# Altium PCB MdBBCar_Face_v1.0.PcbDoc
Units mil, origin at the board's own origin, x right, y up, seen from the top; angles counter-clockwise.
Board outline 2202.88 x 1898.45 mil, 4 copper layers (Top Layer, GND, SIG, Bottom Layer), stack 23.756 mil thick; 53 components, 60 nets, 263 pads, 211 vias.
Unrouted connection lines stored in the file: 2.
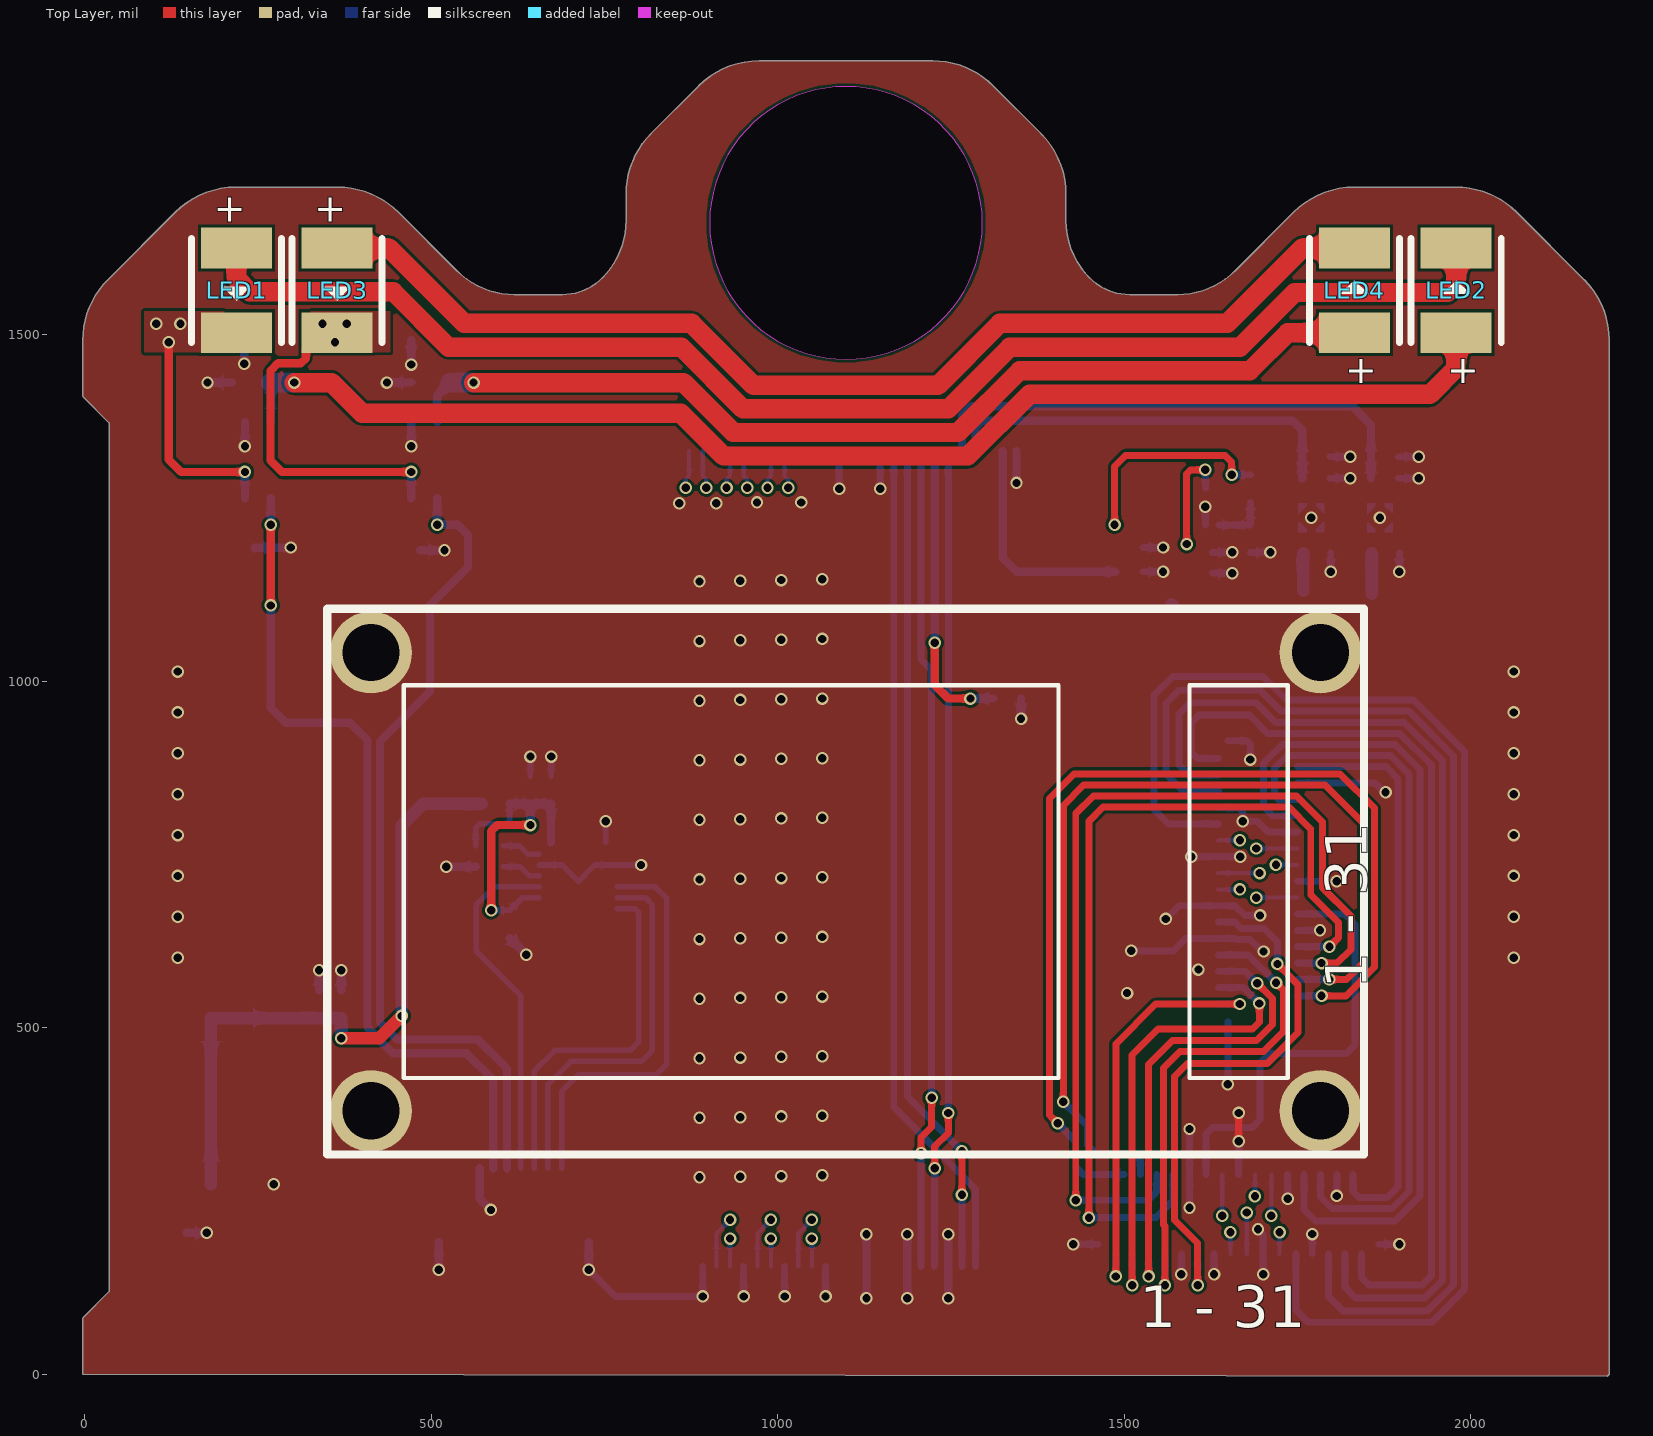
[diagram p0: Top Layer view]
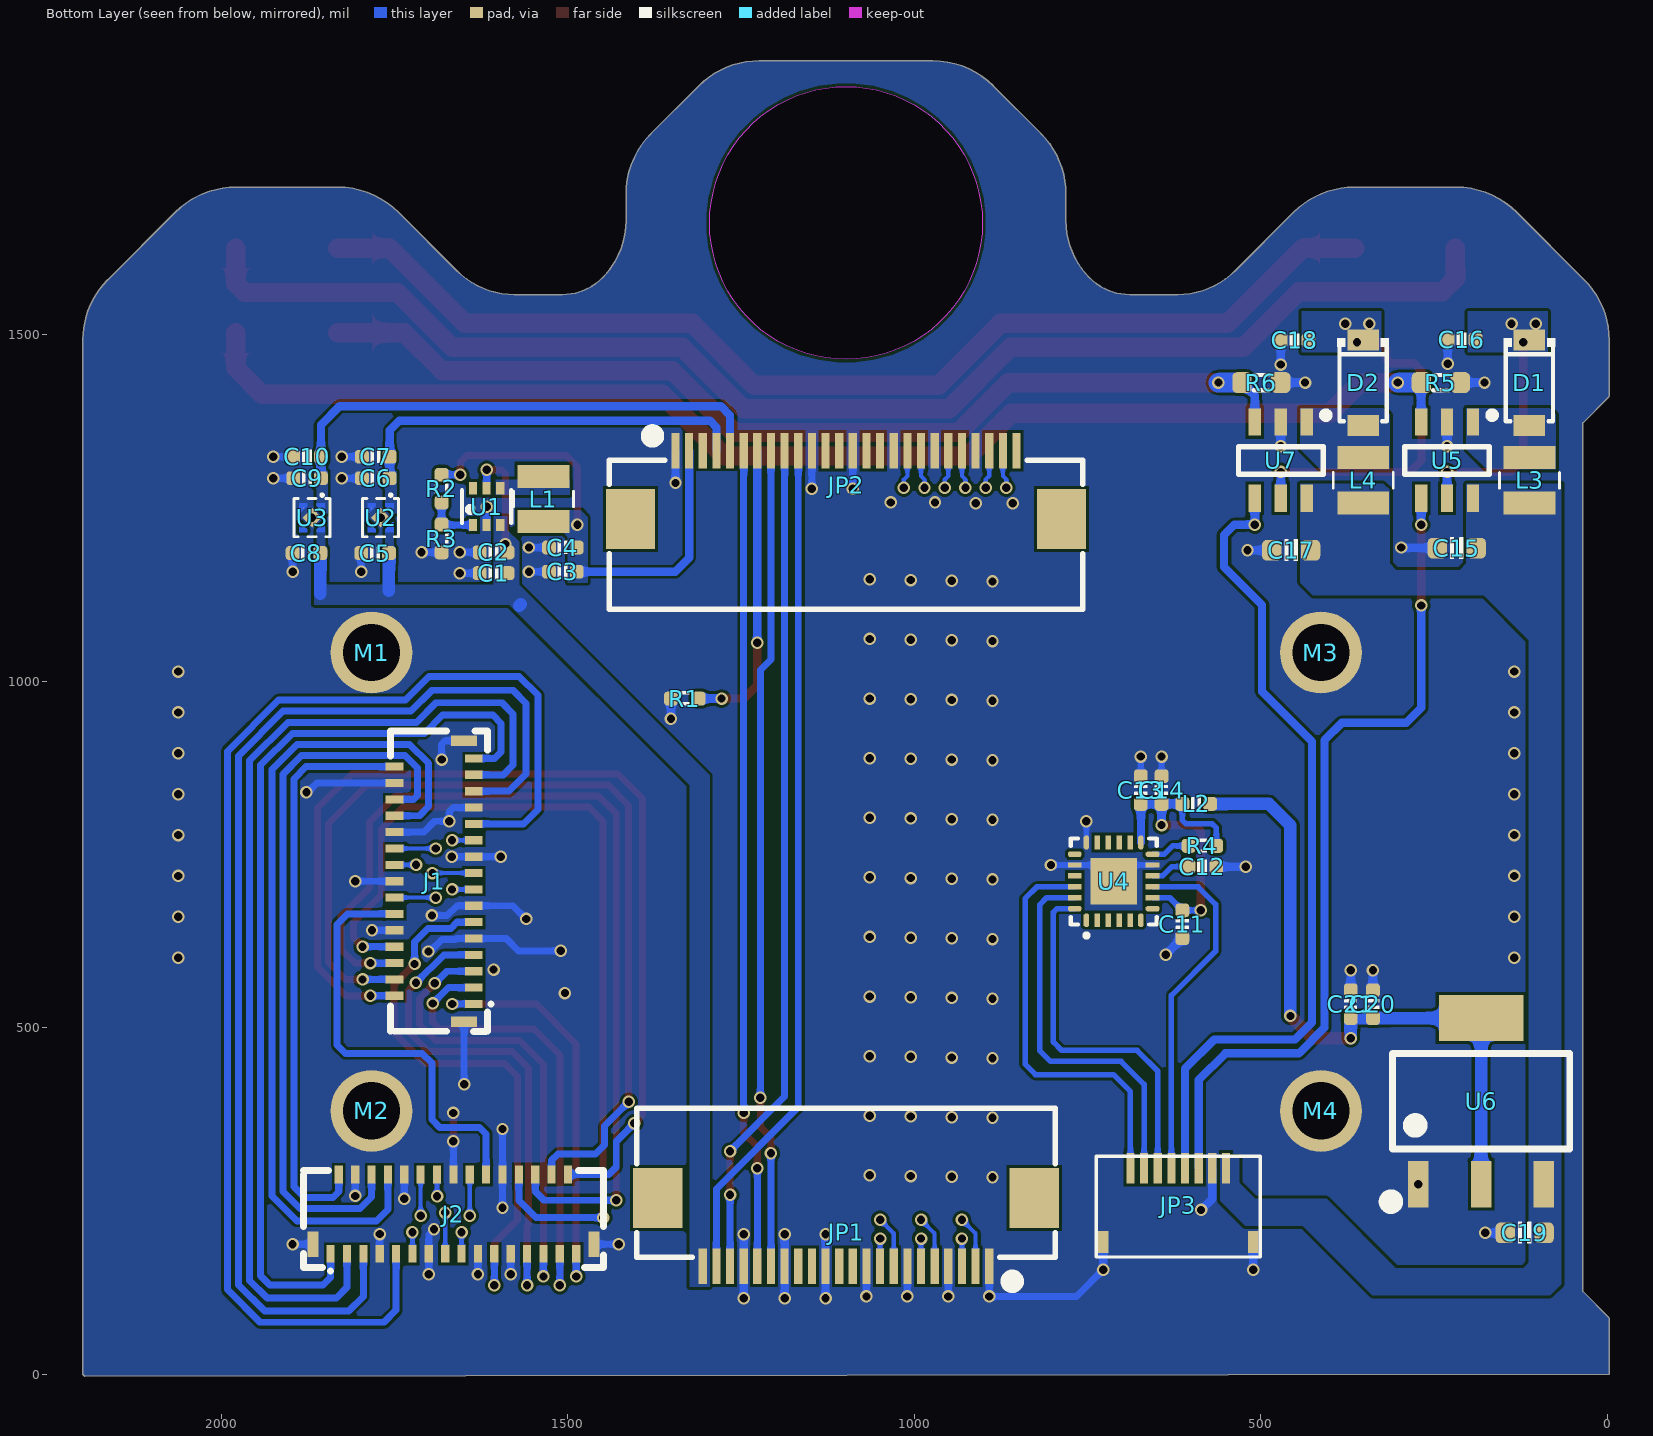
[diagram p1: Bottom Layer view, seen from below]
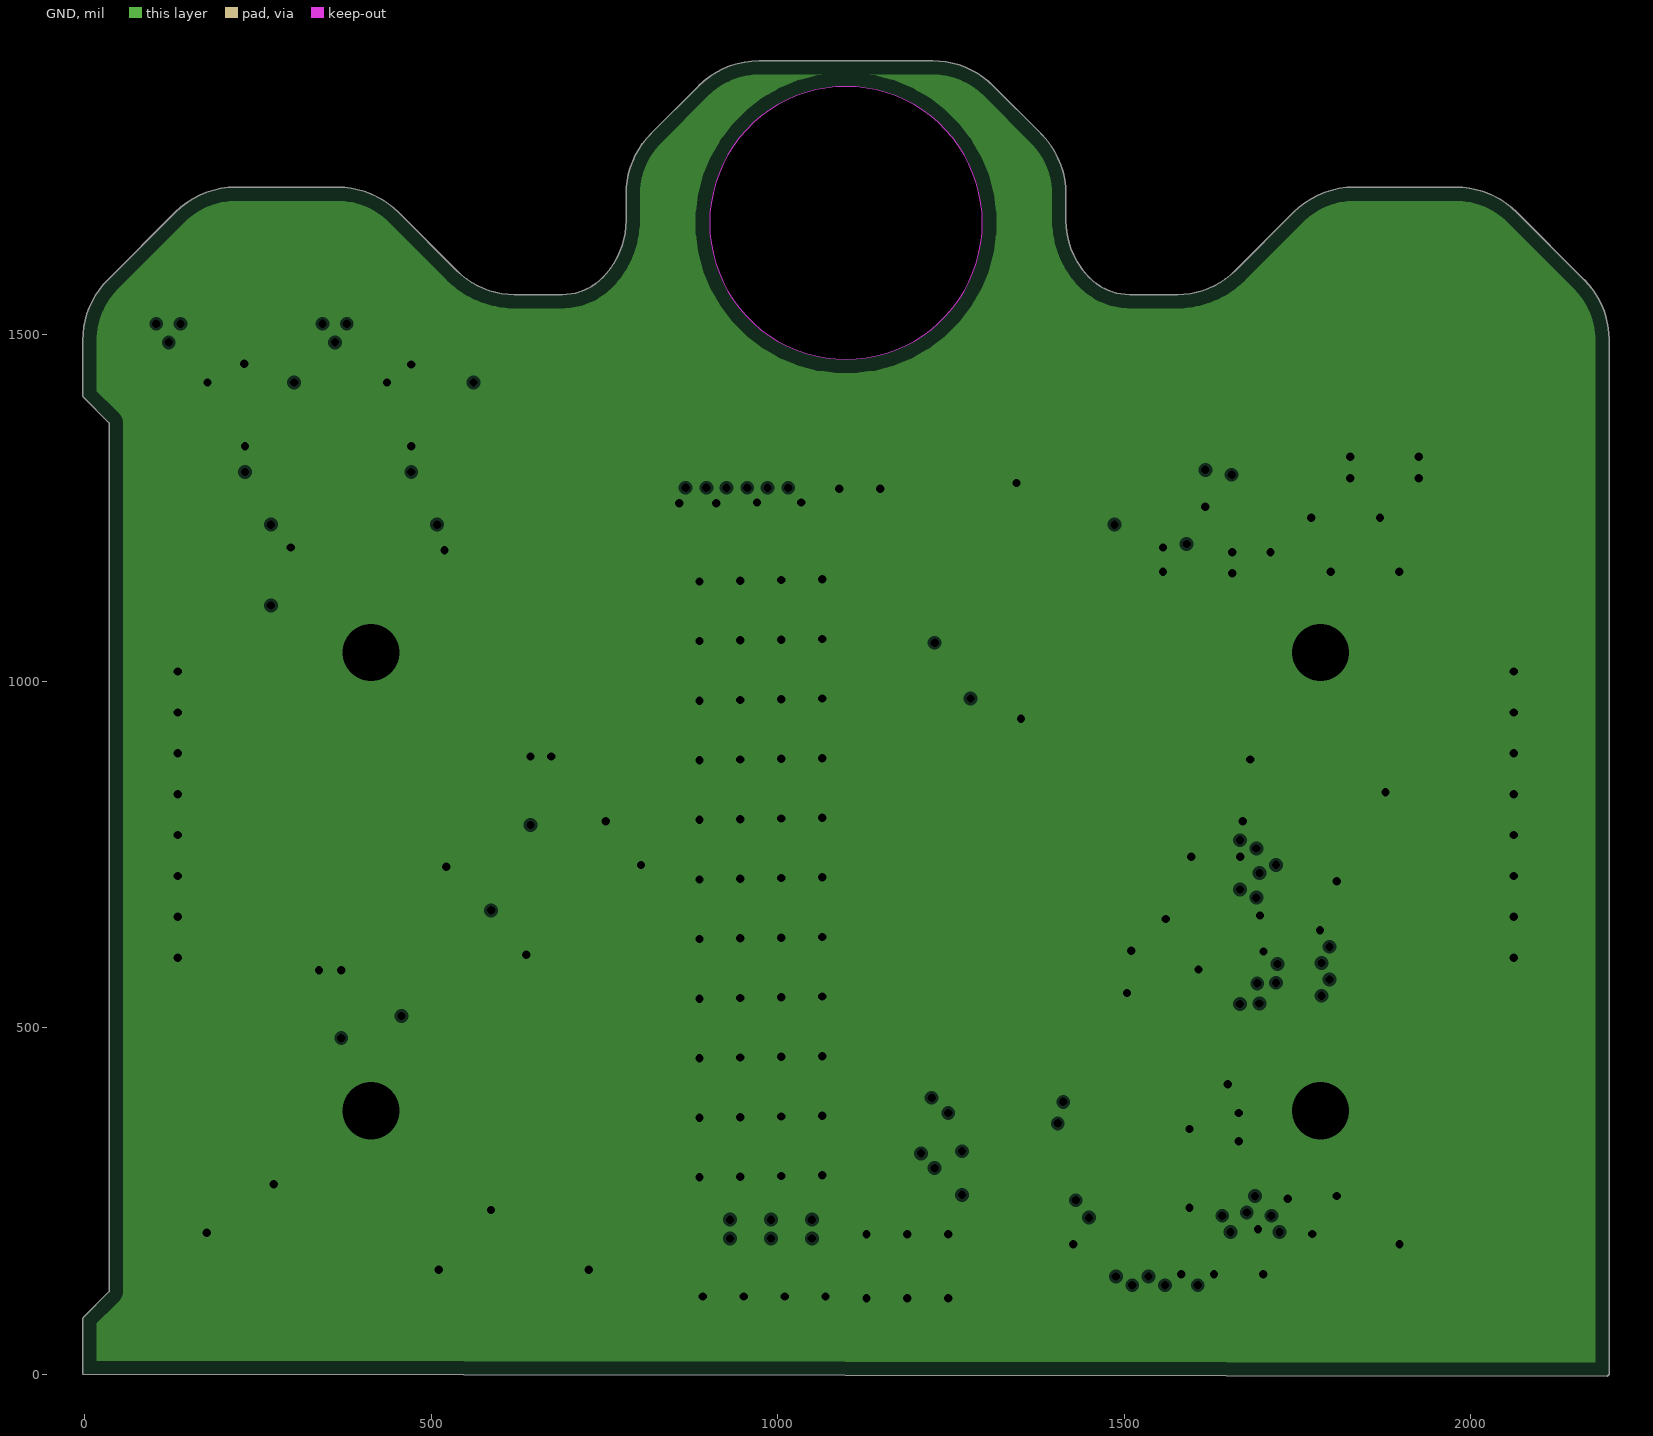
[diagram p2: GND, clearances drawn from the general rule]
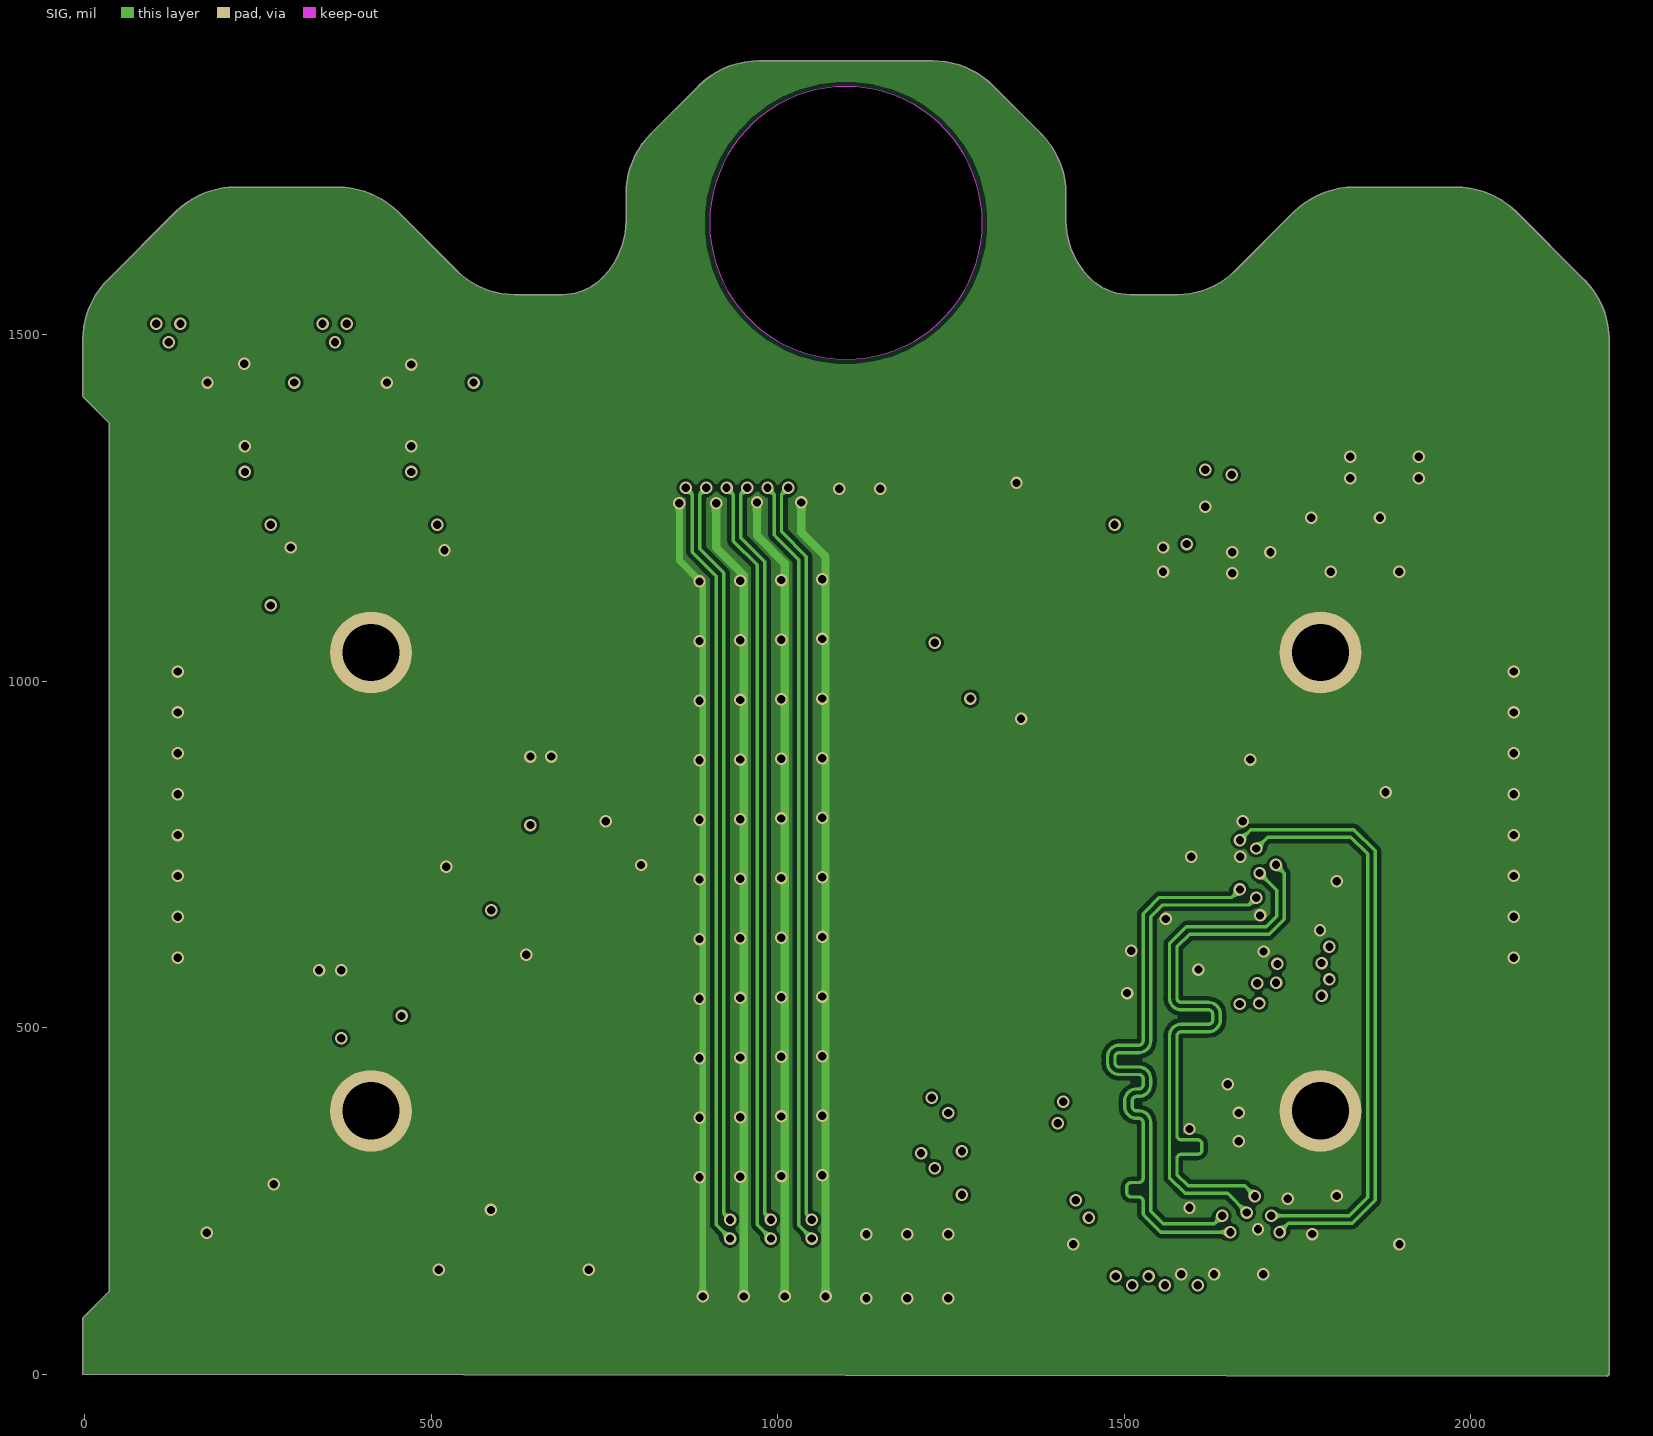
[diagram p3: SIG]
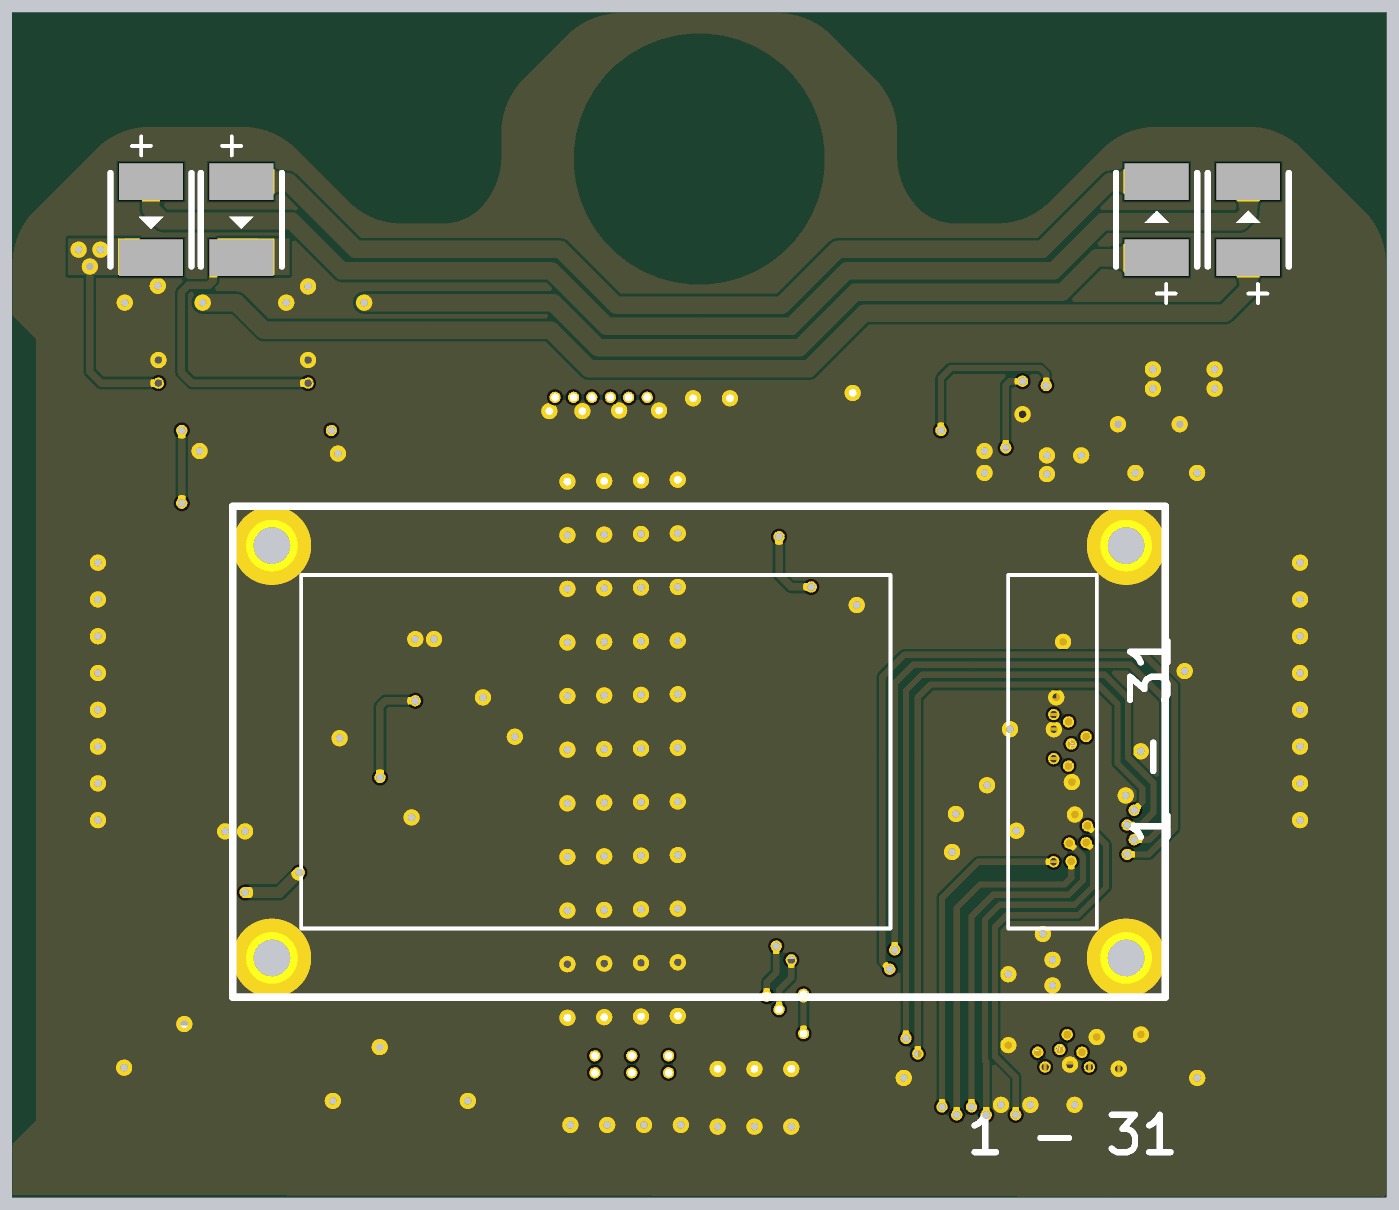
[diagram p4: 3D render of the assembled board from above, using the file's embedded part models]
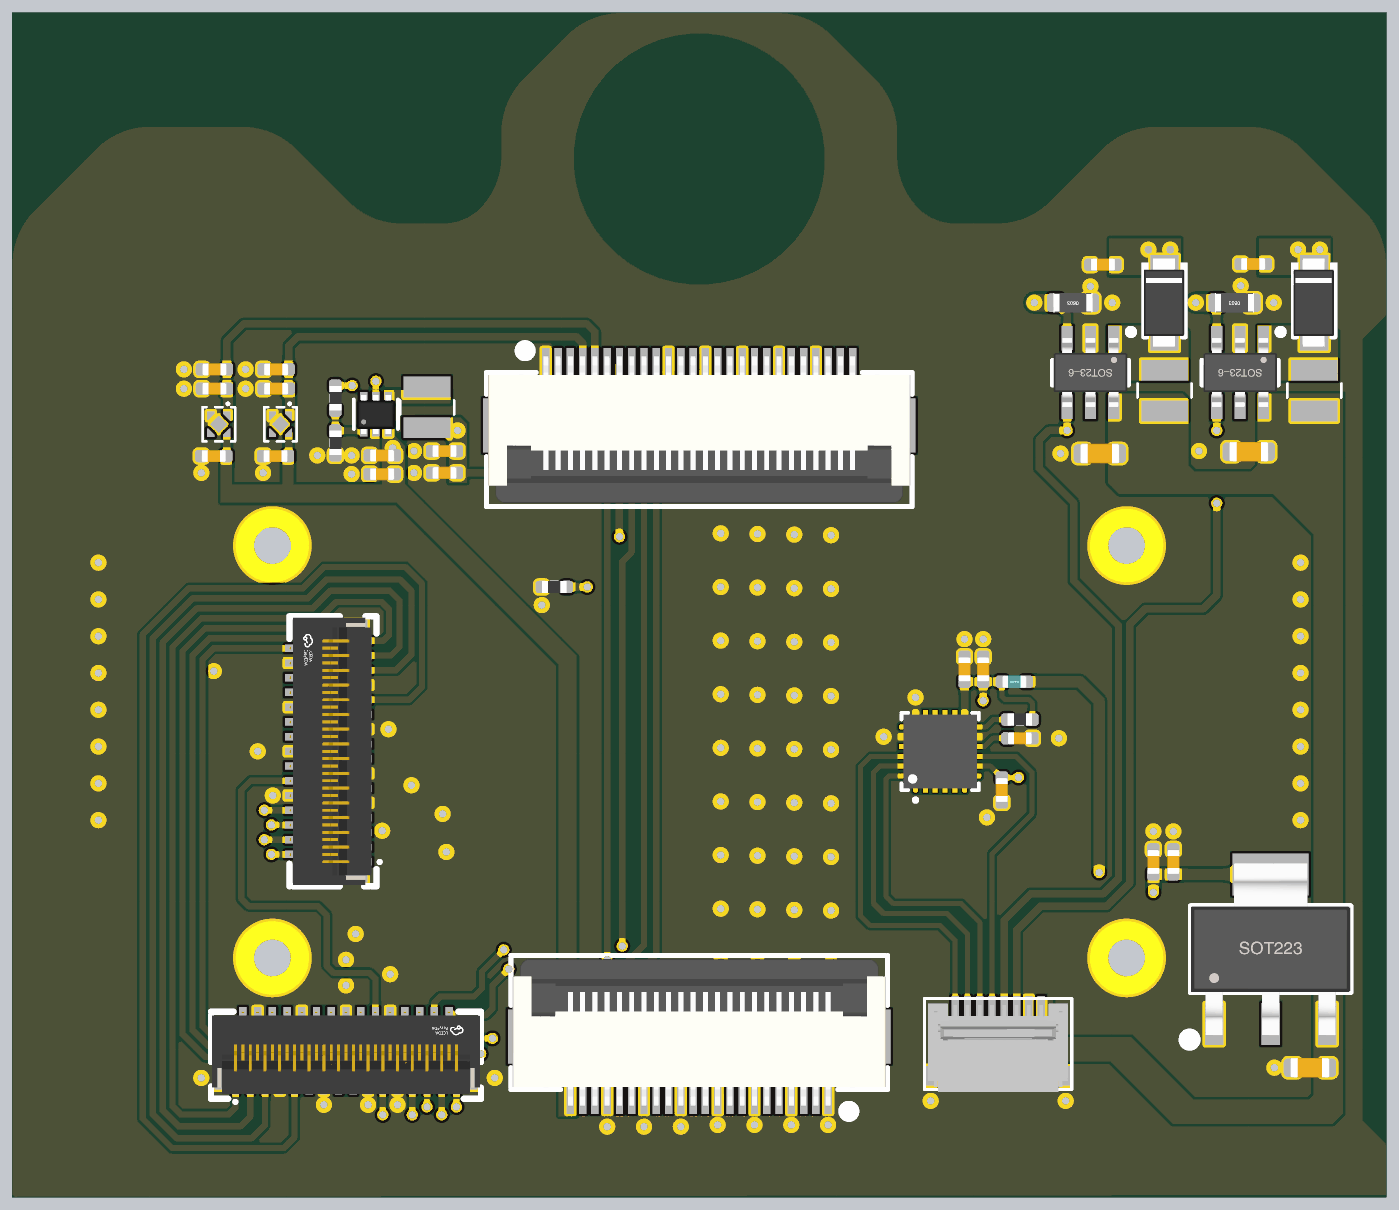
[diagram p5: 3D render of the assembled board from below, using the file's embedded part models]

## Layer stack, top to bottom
Top Solder: solder mask 0.4, Solder Resist, Dk 3.5
Top Layer: signal copper 1.4
Dielectric 2: prepreg 2.8, PP-006, Dk 4.1
GND: plane copper 1.378, net GND
Dielectric 1: dielectric 12.6, FR-4, Dk 4.8
SIG: signal copper 1.378
Dielectric 3: prepreg 2.8, PP-006, Dk 4.1
Bottom Layer: signal copper 1.4
Bottom Solder: solder mask 0.4, Solder Resist, Dk 3.5

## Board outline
-3.02,0 -3.02,80 -2.13,82.13 34.98,119.25 34.98,1372.75 -2.13,1409.87 -3.02,1412 -3.02,1492 cw(c120.71,1492) 33.22,1579.49 130.51,1676.78 cw(c218,1589.29) 218,1713.02 365,1713.02 cw(c365,1589.29) 452.49,1676.78 536.78,1592.49 ccw(c620,1675.71) 620,1558.02 689.15,1558.02 ccw(c689.15,1639.14) 746.51,1581.78 ccw(c663.29,1665) 780.98,1665 780.98,1703 cw(c904.71,1703) 817.22,1790.49 885.94,1859.2 cw(c973.42,1771.71) 973.42,1895.44 1223.42,1895.44 cw(c1223.42,1771.71) 1310.91,1859.2 1379.63,1790.49 cw(c1292.14,1703) 1415.86,1703 1415.86,1665 ccw(c1533.56,1665) 1450.34,1581.78 ccw(c1507.7,1639.14) 1507.7,1558.02 1576.85,1558.02 ccw(c1576.85,1675.71) 1660.07,1592.49 1744.36,1676.78 cw(c1831.85,1589.29) 1831.85,1713.02 1978.85,1713.02 cw(c1978.85,1589.29) 2066.34,1676.78 2163.63,1579.49 cw(c2076.14,1492) 2199.86,1492 2199.86,1422.83 2199.87,0 2196.85,-3.01
cut-out: 901.57,1661.4 ccw(c1098.43,1661.4) 1098.43,1464.55 ccw(c1098.43,1661.4) 1295.28,1661.4 ccw(c1098.43,1661.4) 1098.43,1858.25 ccw(c1098.43,1661.4)

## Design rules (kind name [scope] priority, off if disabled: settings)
Clearance Clearance_1 [OnLayer('Layer 2')] p1: gap=4 ignorepadtopadclearanceinfootprint=FALSE except(6: Arc-Arc Arc-Track Arc-Fill Arc-Poly Arc-Region Track-Track Track-Fill Track-Poly Track-Region Fill-Fill Fill-Poly Fill-Region Poly-Poly Poly-Region Region-Region)
Clearance [All] p2: gap=4 ignorepadtopadclearanceinfootprint=FALSE except(6: Arc-Arc Arc-Track Track-Track)
DiffPairsRouting DiffPairsRouting_1 [InDifferentialPair('MIPI_TX0') Or InDifferentialPair('MIPI_TX1') Or InDifferentialPair('MIPI_TX2') Or InDifferentialPair('CSI_CLK') Or  InDifferentialPair('CSI_D0') Or InDifferentialPair('CSI_D1')] p1: maxlimit=10 minlimit=4 mostfreqgap=6 toplayer_minwidth=4 toplayer_maxwidth=15 toplayer_prefwidth=4.79 midlayer2_minwidth=4.79 midlayer2_maxwidth=15 midlayer2_prefwidth=4.79 bottomlayer_minwidth=4 bottomlayer_maxwidth=15 bottomlayer_prefwidth=4.79 maxuncoupledlength=500
DiffPairsRouting [All] p2: maxlimit=10 minlimit=10 mostfreqgap=10 toplayer_minwidth=15 toplayer_maxwidth=15 toplayer_prefwidth=15 midlayer2_minwidth=15 midlayer2_maxwidth=15 midlayer2_prefwidth=15 bottomlayer_minwidth=15 bottomlayer_maxwidth=15 bottomlayer_prefwidth=15 maxuncoupledlength=500
MatchedLengths MatchedLengths_2 [InNetClass('MIPI_TX2')] p1: tolerance=10 checknetsindiffpair=TRUE checkdiffpairvsdiffpair=FALSE checkxsignals=FALSE checkothers=FALSE
MatchedLengths MatchedLengths_1 [InNetClass('MIPI_TX1')] p2: tolerance=10 checknetsindiffpair=TRUE checkdiffpairvsdiffpair=FALSE checkxsignals=FALSE checkothers=FALSE
MatchedLengths [InNetClass('MIPI_TX0')] p3: tolerance=10 checknetsindiffpair=TRUE checkdiffpairvsdiffpair=FALSE checkxsignals=FALSE checkothers=FALSE
PlaneClearance [All] p1: clearance=4
PlaneConnect [All] p1: planeconnectstyle=Direct reliefexpansion=20 reliefentries=4 reliefconductorwidth=10 reliefairgap=10
PolygonConnect [All] p1: connectstyle=Direct reliefconductorwidth=10 reliefentries=4 polygonreliefangle="90 Angle" airgapwidth=10
RoutingVias [All] p1: holewidth=12 width=50 viastyle="Through Hole" minholewidth=12 minwidth=18 maxholewidth=28 maxwidth=18
SolderMaskExpansion [All] p1: expansion=4 istentingtop=FALSE
Width [All] p1: maxlimit=60 minlimit=3.5 preferedwidth=10
27 further rules are at their usual default settings.

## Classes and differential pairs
net class CSI_: CSI_CLK_N CSI_CLK_P CSI_D0_N CSI_D0_P CSI_D1_N CSI_D1_P
net class MIPI_TX2: MIPI_TX2_N MIPI_TX2_P
net class MIPI_TX1: MIPI_TX1_N MIPI_TX1_P
net class MIPI_TX0: MIPI_TX0_N MIPI_TX0_P
differential pair CSI_D1: +CSI_D1_P -CSI_D1_N
differential pair CSI_D0: +CSI_D0_P -CSI_D0_N
differential pair CSI_CLK: +CSI_CLK_P -CSI_CLK_N
differential pair MIPI_TX2: +MIPI_TX2_P -MIPI_TX2_N
differential pair MIPI_TX1: +MIPI_TX1_P -MIPI_TX1_N
differential pair MIPI_TX0: +MIPI_TX0_P -MIPI_TX0_N

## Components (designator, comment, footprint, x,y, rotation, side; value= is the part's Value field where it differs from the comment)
C1 "10uF" "C 0402_L" 1607,1156 r0 bottom
C2 "100nF" "C 0402_L" 1607,1186 r0 bottom
C3 "10uF" "C 0402_L" 1507,1158 r0 bottom
C4 "10uF" "C 0402_L" 1507,1193 r0 bottom
C5 "1uF" "C 0402_L" 1778,1185 r0 bottom
C6 "1uF" "C 0402_L" 1777,1293 r0 bottom
C7 "0.1uF" "C 0402_L" 1777,1324 r0 bottom
C8 "1uF" "C 0402_L" 1877,1185 r0 bottom
C9 "1uF" "C 0402_L" 1876,1293 r0 bottom
C10 "0.1uF" "C 0402_L" 1876,1324 r0 bottom
C11 "100nF" "C 0402_L" 613.06,649.4 r90 bottom
C12 "100nF" "C 0402_L" 584.06,732.4 r0 bottom
C13 "100nF" "C 0402_L" 673,843 r90 bottom
C14 "2.2uF" "C 0402_L" 643,843 r90 bottom
C15 "10uF" "C 0603_L" 217,1192 r180 bottom
C16 "0.47uF" "C 0402_L" 210,1493 r0 bottom
C17 "10uF" "C 0603_L" 456,1189 r180 bottom
C18 "0.47uF" "C 0402_L" 451,1492 r0 bottom
C19 "10uF" "C 0603_L" 119,204 r180 bottom
C20 "1uF" "C 0402_L" 338,534 r90 bottom
C21 "0.1uF" "C 0402_L" 370,534 r90 bottom
D1 "DSS34" SOD-123FL 115,1431 r270 bottom
D2 "DSS34" SOD-123FL 355,1431 r270 bottom
J1 "FPC-31P(交错脚)" "FPC 1H-WS-31P" 1692.91,711.42 r90 bottom
J2 "FPC-31P(交错脚)" "FPC 1H-WS-31P" 1665,231 r180 bottom
JP1 "FPC1.0-22P" "FPC0.5 2H-WS-22P" 1098.43,254 r0 bottom
JP2 "FPC1.0-26P" "FPC0.5 2H-WS-26P" 1098.43,1234 r180 bottom
JP3 "FPC-8P" "FPC0.5 1H-WS-8P-NARROW" 619,240 r90 bottom
L1 "FTC252012S1R0" 252012 1535,1263 r270 bottom
L2 "BLM15AX102SN1D" "L 0402" 593,823 r0 bottom
L3 "FTC252010S4R7MBCA" 252012 112,1290 r90 bottom
L4 "FTC252010S4R7MBCA" 252012 352,1290 r90 bottom
LED1 "红外" "LED 3528-2Pin" 219,1564 r90 top
LED2 "红外" "LED 3528-2Pin" 1979,1564 r270 top
LED3 "白色" "LED 3528-2Pin" 364,1564 r90 top
LED4 "白色" "LED 3528-2Pin" 1832,1564 r270 top
M1 "NUT" SMT-NUT-M1610 1783.07,1041.41 r180 bottom
M2 "NUT" SMT-NUT-M1610 1783.07,379.99 r180 bottom
M3 "NUT" SMT-NUT-M1610 412.99,1041.41 r180 bottom
M4 "NUT" SMT-NUT-M1610 412.99,379.99 r180 bottom
R1 "10K" "R 0402_L" 1331,975 r0 bottom
R2 "10K" "R 0402_L" 1682,1278 r270 bottom
R3 "10K" "R 0402_L" 1682,1206 r270 bottom
R4 "10K" "R 0402_L" 584.06,762.4 r180 bottom
R5 "2R" "R 0603_L" 240,1431 r0 bottom
R6 "1R" "R 0603_L" 499,1431 r0 bottom
U1 "RT5760DHGH6F" SOT563-6 1617,1252 r180 bottom
U2 "WL2836D28-4/TR" DFN4-EP(1X1) 1770,1236 r0 bottom
U3 "WL2836D18-4/TR" DFN4-EP(1X1) 1869,1236 r0 bottom
U4 "MPU6500" "QFN24 3X3" 712.13,711.2 r180 bottom
U5 "AP3031KTR-G1" SOT23-6L 231,1319 r0 bottom
U6 "AMS1117-3V3" SOT223_L 182,394 r180 bottom
U7 "AP3031KTR-G1" SOT23-6L 471,1319 r0 bottom

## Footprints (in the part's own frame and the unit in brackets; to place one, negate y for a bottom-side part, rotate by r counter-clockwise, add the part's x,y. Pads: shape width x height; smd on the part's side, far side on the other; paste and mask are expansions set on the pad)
252012 [mm]
  rect 0.85x1.905 smd: 1(-0.83,0) 2(0.83,0)
  silkscreen extent -0.29,-1.1 0.29,1.1, body extent -1.25,-1 1.25,1, height 1.2
"C 0402_L" [mil] "无极性贴片电容"
  rrect50% 20x20 smd: 1(20,0) 2(-20,0)
  silkscreen extent -6,-9 6,9, body extent -20,-10 20,10, height 20
"C 0603_L" [mil] "无极性贴片电容"
  rrect50% 28x30 smd: 1(-28,0) 2(28,0)
  silkscreen extent -10,-15 10,15, body extent -31,-16 31,16, height 31
DFN4-EP(1X1) [mm]
  round 0.025 smd: 1(-0.325,-0.325) 2(0.325,-0.35) 3(0.325,0.35) 4(-0.325,0.35)
  rect 0.5x0.5 smd rot 45: 5(0,0)
  Top Layer region: 0.175,0.525 0.475,0.525 0.475,0.175 0.425,0.175 0.175,0.425 0.175,0.525
  Top Layer region: -0.475,0.175 -0.475,0.525 -0.175,0.525 -0.175,0.475 -0.175,0.425 -0.425,0.175 -0.475,0.175
  Top Layer region: -0.175,-0.525 -0.475,-0.525 -0.475,-0.125 -0.175,-0.425 -0.175,-0.525
  Top Layer region: 0.475,-0.175 0.475,-0.525 0.175,-0.525 0.175,-0.425 0.425,-0.175 0.475,-0.175
  silkscreen extent -0.66,-0.88 0.66,0.7
"FPC0.5 1H-WS-8P-NARROW" [mm] "前插后翻"
  rect 0.8x0.4 smd: 0(-1.25,-2.75) 0(-1.25,2.75)
  rect 1.1x0.3 smd: 1(1.453,1.75) 2(1.453,1.25) 3(1.453,0.75) 4(1.453,0.25) 5(1.453,-0.25) 6(1.453,-0.75) 7(1.453,-1.25) 8(1.453,-1.75)
  silkscreen extent -1.8,-3 1.9,3, body extent -1.9,-2.85 1.7,2.85, height 1.88
"FPC0.5 2H-WS-22P" [mm] "长：15.2mm，宽：5.2mm，高：2mm"
  rect 1.8x2.2 smd: 0(-6.9,0) 0(6.9,0)
  rect 0.3x1.3 smd: 1(-5.25,2.497) 2(-4.75,2.497) 3(-4.25,2.497) 4(-3.75,2.497) 5(-3.25,2.497) 6(-2.75,2.497) 7(-2.25,2.497) 8(-1.75,2.497) 9(-1.25,2.497) 10(-0.75,2.497) 11(-0.25,2.497) 12(0.25,2.497) 13(0.75,2.497) 14(1.25,2.497) 15(1.75,2.497) 16(2.25,2.497) 17(2.75,2.497) 18(3.25,2.497) 19(3.75,2.497) 20(4.25,2.497) 21(4.75,2.497) 22(5.25,2.497)
  silkscreen extent -7.68,-3.3 7.68,3.23, body extent -7.6,-3.15 7.6,2.85, height 2
"FPC0.5 2H-WS-26P" [mm] "长：17.2mm，宽：5.2mm，高：2mm"
  rect 1.8x2.2 smd: 0(-7.9,0) 0(7.9,0)
  rect 0.3x1.3 smd: 1(-6.25,2.497) 2(-5.75,2.497) 3(-5.25,2.497) 4(-4.75,2.497) 5(-4.25,2.497) 6(-3.75,2.497) 7(-3.25,2.497) 8(-2.75,2.497) 9(-2.25,2.497) 10(-1.75,2.497) 11(-1.25,2.497) 12(-0.75,2.497) 13(-0.25,2.497) 14(0.25,2.497) 15(0.75,2.497) 16(1.25,2.497) 17(1.75,2.497) 18(2.25,2.497) 19(2.75,2.497) 20(3.25,2.497) 21(3.75,2.497) 22(4.25,2.497) 23(4.75,2.497) 24(5.25,2.497) 25(5.75,2.497) 26(6.25,2.497)
  silkscreen extent -8.68,-3.3 8.68,3.23, body extent -8.6,-3.15 8.6,2.85, height 2
"FPC 1H-WS-31P" [mm]
  rect 0.3x0.65 smd: 1(-4.5,-1.453) 2(-4.2,1.453) 3(-3.9,-1.453) 4(-3.6,1.453) 5(-3.3,-1.453) 6(-3,1.453) 7(-2.7,-1.453) 8(-2.4,1.453) 9(-2.1,-1.453) 10(-1.8,1.453) 11(-1.5,-1.453) 12(-1.2,1.453) 13(-0.9,-1.453) 14(-0.6,1.453) 15(-0.3,-1.453) 16(0,1.453) 17(0.3,-1.453) 18(0.6,1.453) 19(0.9,-1.453) 20(1.2,1.453) 21(1.5,-1.453) 22(1.8,1.453) 23(2.1,-1.453) 24(2.4,1.453) 25(2.7,-1.453) 26(3,1.453) 27(3.3,-1.453) 28(3.6,1.453) 29(3.9,-1.453) 30(4.2,1.453) 31(4.5,-1.453)
  rect 0.4x0.95 smd: 32(-5.15,-1.103) 33(5.15,-1.103)
  silkscreen extent -5.5,-2.08 5.5,1.6, body extent -5.45,-1.75 5.45,1.65, height 1
"L 0402" [mil] "小功率贴片电感"
  rrect50% 20x20 smd: 1(20,0) 2(-20,0)
  silkscreen extent -6,-9 6,9, body extent -20,-10 20,10, height 20
"LED 3528-2Pin" [mm] "2脚，3528LED"
  rect 1.5x2.6 smd paste+0 mask+0.05: 1(1.55,0) 2(-1.55,0)
  silkscreen extent -1.9,-1.65 1.91,1.65, body extent -1.77,-1.4 1.73,1.4, height 1.95
"QFN24 3X3" [mm]
  oct 0.2x0.505 smd paste-100 mask+0.051: 1(-1,-1.427) 6(1,-1.427) 13(1,1.427) 18(-1,1.427)
  rect 0.2x0.505 smd paste-100 mask+0.051: 2(-0.6,-1.427) 3(-0.2,-1.427) 4(0.2,-1.427) 5(0.6,-1.427) 14(0.6,1.427) 15(0.2,1.427) 16(-0.2,1.427) 17(-0.6,1.427)
  oct 0.505x0.2 smd paste-100 mask+0.051: 7(1.427,-1) 12(1.427,1) 19(-1.427,1) 24(-1.427,-1)
  rect 0.505x0.2 smd paste-100 mask+0.051: 8(1.427,-0.6) 9(1.427,-0.2) 10(1.427,0.2) 11(1.427,0.6) 20(-1.427,0.6) 21(-1.427,0.2) 22(-1.427,-0.2) 23(-1.427,-0.6)
  rect 1.7x1.7 smd paste-100 mask+0.051: 25(0,0)
  silkscreen extent -1.58,-2.05 1.58,1.58, body extent -1.5,-1.5 1.5,1.5, height 0.98
"R 0402_L" [mil] "1/16W贴片电阻"
  rrect50% 20x20 smd: 1(20,0) 2(-20,0)
  silkscreen extent -6,-9 6,10, body extent -20,-10 20,10, height 14
"R 0603_L" [mil] "1/10W贴片电阻"
  rrect50% 28x30 smd: 1(-28,0) 2(28,0)
  silkscreen extent -11,-11 11,11, body extent -31,-16 31,16, height 16
SMT-NUT-M1610 [mm]
  round 3 hole 2.1: 1(0,0)
  body extent -1.5,-1.5 1.5,1.5, height 1
SOD-123FL [mil]
  rect 30x45.28 smd: 1(-61.3,2.79) 2(61.96,2.79)
  silkscreen extent -64,-34 56,40, body extent -71,-30 71,34, height 37
SOT23-6L [mm] "3x1.6x1.1mm(长宽高)"
  rect 0.45x1 smd: 1(-0.95,-1.397) 2(0,-1.397) 3(0.95,-1.397) 4(0.95,1.397) 5(0,1.397) 6(-0.95,1.397)
  silkscreen extent -1.77,-1.78 1.55,0.51, body extent -1.5,-1.4 1.5,1.4, height 1.15
SOT223_L [mm] "6.4x7x1.6mm(长宽高)"
  rect 0.75x1.7 smd: 1(-2.3,-3.048) 2(0,-3.048) 3(2.3,-3.048)
  rect 3.1x1.7 smd: 2(0,3.048)
  silkscreen extent -3.5,-3.88 3.25,1.75, body extent -3.25,-3.51 3.25,3.51, height 1.65
SOT563-6 [mm]
  rect 0.3x0.45 smd: 1(-0.5,-0.675) 2(0,-0.675) 3(0.5,-0.675) 4(0.5,0.675) 5(0,0.675) 6(-0.5,0.675)
  silkscreen extent -0.9,-0.6 0.9,0.6, body extent -0.8,-0.81 0.8,0.79, height 0.55

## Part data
C1 C2 C3 C4 C5 C6 C7 C8 C9 C10 C11 C12 C13 C14 C15 C16 C17 C18 C19 C20 C21: library part C, "无极性贴片电容"
D1 D2: "肖特基二极管"
J1 J2 JP3: "FPC连接器"
JP1: library part FPC-22P, "FPC连接器"
JP2: library part FPC-26P, "FPC连接器"
L1 L3 L4: library part L-CD, "贴片功率电感"
L2: library part L, "小功率贴片电感"
LED1 LED2 LED3 LED4: library part LED-SMD, "贴片LED"
M1 M2 M3 M4: library part SMTNUT, "SMT表贴螺母"
R1 R2 R3 R4 R5 R6: library part R, "贴片电阻"
U1: library part RT5760, "2.5V~6V输入 / 1A输出 / 2.2MHz"
U2 U3: library part WL2836DXX-4/TR, "LDO 300mA / 输入 1.4~5.5V / PSRR 78dB"
U4: "6轴IMU"
U5 U7: library part AP3031, "LED驱动"
U6: library part AMS1117, "三端稳压芯片"

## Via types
v1: diameter 18, hole 12, Top Layer to Bottom Layer, 211 vias

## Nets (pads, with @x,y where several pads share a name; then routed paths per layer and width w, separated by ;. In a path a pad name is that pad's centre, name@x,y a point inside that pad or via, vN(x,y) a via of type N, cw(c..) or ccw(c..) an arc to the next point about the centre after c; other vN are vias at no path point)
AVCC_3V3: C20.2 C21.2 L2.2 U6.2 | length 961.1
  Top Layer w18: v1(370,485) 425,485 v1(457,517)
  Bottom Layer w18: U6.2@182,274 182,514 C20.2 C21.2 v1(370,485) ; v1(457,517) 457,792 488,823 L2.2
AVDD_2V8: C6.2 C7.2 JP2.4 U2.1 | length 584.5
  Bottom Layer w12: JP2.4 1285.43,1366.43 1295,1376 1743,1376 1757,1362 C7.2 C6.2
C1: J1.1 J2.31 | length 602.5
  Top Layer w10: v1(1487.84,141.07) 1487.84,476.84 1545.25,534.25 v1(1666.87,534.25)
  Bottom Layer w10: v1(1487.84,141.07) J2.31 ; J1.1 v1(1666.87,534.25)
C2: J1.2 J2.30 | length 1483.6
  Top Layer w10: v1(1404,362) 1392,374 1392,831 1427.4,866.4 1811.6,866.4 1861,817 1861,587.37 1819.69,546.06 v1(1784.69,546.06)
  Bottom Layer w10: v1(1404,362) 1430,336 1430,299 1440.8,288.2 J2.30 ; J1.2 v1(1784.69,546.06)
C3: J1.3 J2.29 | length 676.7
  Top Layer w10: v1(1511.45,128.3) 1511.45,460.45 1549,498 1685,498 1695,508 v1(1695,535)
  Bottom Layer w10: v1(1511.45,128.3) J2.29 ; J1.3 1672.13,557.87 v1(1695,535)
C4: J1.4 J2.28 | length 1384.6
  Top Layer w10: v1(1412,393) 1412,821 1441.4,850.4 1789.6,850.4 1845,795 1845,594 1820.68,569.68 v1(1796.07,569.68)
  Bottom Layer w10: v1(1412,393) 1447,358 1447,331 1460,318 1514,318 1523.27,308.74 J2.28 ; J1.4 v1(1796.07,569.68)
C5: J1.5 J2.27 | length 673.7
  Top Layer w10: v1(1535.07,141.07) 1535.07,447.07 1569.4,481.4 1691.03,481.4 1714,504.37 1714,542 v1(1692,564)
  Bottom Layer w10: v1(1535.07,141.07) J2.27 ; J1.5 1674.51,581.49 v1(1692,564)
C6: J1.6 J2.26 | length 1372.6
  Top Layer w10: v1(1430,251) 1430,809 1455.4,834.4 1748.6,834.4 1786,797 1786,702 1827,661 1827,613 1807.31,593.31 v1(1784.69,593.31)
  Bottom Layer w10: v1(1430,251) 1534,251 1546.89,263.89 J2.26 ; J1.6 v1(1784.69,593.31)
C7: J1.7 J2.25 | length 729.8
  Top Layer w10: v1(1558.7,128.3) 1558.7,213.67 1556.7,215.67 1556.7,441.7 1580.4,465.4 1700.73,465.4 1730,494.67 1730,554 v1(1719,565)
  Bottom Layer w10: v1(1558.7,128.3) J2.25 ; J1.7 1678.88,605.12 v1(1719,565)
C8: J1.8 J2.24 | length 1320.8
  Top Layer w10: v1(1449,226) 1449,798 1469.4,818.4 1737.6,818.4 1769.06,786.94 1769.06,691.94 1809,652 1809,629.86 v1(1796.07,616.93)
  Bottom Layer w10: v1(1449,226) 1546,226 1570.52,250.51 J2.24 ; J1.8 v1(1796.07,616.93)
C11: J1.11 J2.21 | length 805.6
  Top Layer w10: v1(1605.94,128.3) 1605.94,189.05 1572.7,222.3 1572.7,429.7 1591.4,448.4 1706.36,448.4 1751,493.04 1751,562 v1(1721,592)
  Bottom Layer w10: v1(1605.94,128.3) J2.21 ; J1.11 1659.64,652.36 1668.76,643.24 1701.76,643.24 1721,624 v1(1721,592)
C12: J1.12 J2.20 | length 637.9
  Bottom Layer w10: J2.20 1617.76,346.63 1627.13,356 1684.72,356 1696,367.28 1696,449 1710,463 1821,463 1833,475 1833,649 1817.83,664.17 J1.12
C23: J1.23 J2.9 | length 1898.7
  Bottom Layer w10: J1.23 1563.88,794.09 1543.06,814.91 1543.06,980.06 1570,1007 1700,1007 1734.23,972.77 1917.23,972.77 1991.06,898.94 1991.06,122.18 1943.88,75 1765,75 1747.68,92.32 J2.9
C24: J1.24 J2.8 | length 1224.9
  Bottom Layer w10: J1.24 1714.1,805.9 1701,819 1701,881.71 1728.06,908.77 1890.72,908.77 1927.06,872.43 1927.06,257.26 1890.8,221 1776,221 1759.48,237.51 J2.8
C26: J1.26 J2.6 | length 1067.6
  Bottom Layer w10: J1.26 1722.86,829.53 1717,835.39 1717,875.08 1734.69,892.77 1884.09,892.77 1911.06,865.8 1911.06,263.89 1886.18,239 1799.54,239 1783.1,255.44 J2.6
C27: J1.27 J2.5 | length 1679.8
  Bottom Layer w10: J1.27 1584.66,841.34 1560,866 1560,968 1579,987 1696,987 1726.23,956.77 1910.6,956.77 1975.06,892.31 1975.06,128.81 1937.25,91 1816,91 1794.93,112.07 J2.5
C29: J1.29 J2.3 | length 1513.8
  Bottom Layer w10: J1.29 1593.04,864.96 1579,879 1579,953 1595,969 1690,969 1718.23,940.77 1903.97,940.77 1959.06,885.68 1959.06,135.44 1933.63,110 1834,110 1818.55,125.45 J2.3
C30: J1.30 J2.2 | length 840.2
  Bottom Layer w10: J1.30 1877.46,876.77 1895.06,859.17 1895.06,270.51 1879.55,255 1839,255 1830.35,263.64 J2.2
C31: J1.31 J2.1 | length 1348.1
  Bottom Layer w10: J1.31 1605.62,888.58 1596,898.2 1596,939 1608,951 1680.46,951 1706.69,924.77 1897.35,924.77 1943.06,879.05 1943.06,142.06 1930,129 1853,129 1842.16,139.84 J2.1
CAM_3V3: C1.2 C2.2 C5.2 C8.2 JP1.22 U1.3 U1.5 U2.3 U2.4 U3.3 U3.4 | length 273
  Top Layer w10: v1(1590,1198) 1590,1299.14 1595.86,1305 v1(1617,1305)
  Bottom Layer w10: U1.5 v1(1617,1305)
  Bottom Layer w18: 1568,1111 1570,1109 ; 1758,1130.46 C5.2 ; 1857,1126.34 C8.2
CAM_MCLK: JP1.18 JP2.6 | length 1184.8
  Top Layer w10: v1(1226.38,297.38) 1226.38,328.38 1246.06,348.06 v1(1246.06,376.94)
  Bottom Layer w10: JP1.18 v1(1226.38,297.38) ; v1(1246.06,376.94) JP2.6
CAM_PWDN: JP2.7 R1.2 | length 430.4
  Top Layer w12: v1(1226.38,1055.62) 1226.38,994.62 1246,975 v1(1278,975)
  Bottom Layer w12: v1(1226.38,1055.62) JP2.7 ; v1(1278,975) R1.2
CAM_RST: JP1.17 JP2.8 | length 1189.3
  Top Layer w10: v1(1206.69,318.69) 1206.69,341.43 1222,356.74 v1(1222,399)
  Bottom Layer w10: JP1.17 v1(1206.69,318.69) ; JP2.8 1206.69,1031.31 1222,1016 v1(1222,399)
CAM_SCL: JP1.20 JP2.9 | length 1209.2
  Top Layer w10: v1(1265.75,258.75) v1(1265.75,321.75)
  Bottom Layer w10: JP2.9 1187.01,400.49 v1(1265.75,321.75) ; JP1.20 v1(1265.75,258.75)
CAM_SDA: JP1.21 JP2.10 | length 1225.5
  Bottom Layer w10: JP2.10 1167.32,385.68 1285.43,267.57 JP1.21
CSI_CLK_N: JP1.2 JP2.24 | length 1209
  SIG w4.79: v1(896.89,1279.16) 887.36,1269.63 887.36,1190.9 922,1156.26 922,232.1 v1(931.1,223)
  Bottom Layer w6: JP2.24 891.73,1296.16 896.89,1291 v1(896.89,1279.16) ; JP1.2 911.42,203.31 v1(931.1,223)
CSI_CLK_P: JP1.3 JP2.25 | length 1205.3
  SIG w4.79: v1(867.05,1279.16) 876.57,1269.63 876.57,1186.43 911.21,1151.79 911.21,215.68 v1(931.1,195.79)
  Bottom Layer w6: v1@866.89,1279.16 866.89,1291 872.05,1296.16 JP2.25 ; JP1.3 v1(931.1,195.79)
CSI_D0_N: JP1.5 JP2.21 | length 1209
  SIG w4.79: v1(955.94,1279.16) 946.42,1269.63 946.42,1206.84 981,1172.26 981,232.16 v1(990.16,223)
  Bottom Layer w6: JP2.21 950.79,1296.16 955.94,1291 v1(955.94,1279.16) ; JP1.5 970.47,203.31 v1(990.16,223)
CSI_D0_P: JP1.6 JP2.22 | length 1205.3
  SIG w4.79: v1(926.1,1279.16) 935.63,1269.63 935.63,1202.37 970.21,1167.79 970.21,215.74 v1(990.16,195.79)
  Bottom Layer w6: v1@925.94,1279.16 925.94,1291 931.1,1296.16 JP2.22 ; JP1.6 v1(990.16,195.79)
CSI_D1_N: JP1.8 JP2.18 | length 1209
  SIG w4.79: v1(1015,1279.16) 1005.47,1269.63 1005.47,1215.53 1041,1180 1041,231.21 v1(1049.21,223)
  Bottom Layer w6: JP2.18 1009.84,1296.16 1015,1291 v1(1015,1279.16) ; JP1.8 1029.53,203.31 v1(1049.21,223)
CSI_D1_P: JP1.9 JP2.19 | length 1205.3
  SIG w4.79: v1(985.16,1279.16) 994.68,1269.63 994.68,1211.06 999.37,1206.37 1030.21,1175.53 1030.21,214.79 v1(1049.21,195.79)
  Bottom Layer w6: v1@985,1279.16 985,1291 990.16,1296.16 JP2.19 ; JP1.9 v1(1049.21,195.79)
DOVDD_1V8: C9.2 C10.2 JP2.5 U3.1 | length 735.4
  Bottom Layer w12: JP2.5 1265.75,1383.75 1279,1397 1829,1397 1856,1370 C10.2 C9.2
DVDD_1V2: C3.2 C4.2 JP2.2 L1.2 R2.2 | length 633.8
  Top Layer w10: v1(1486,1226) 1486,1309.92 1502.08,1326 1645.68,1326 1655,1316.68 v1(1655,1298)
  Bottom Layer w10: v1(1655,1298) R2.2
  Bottom Layer w12: JP2.2 1324.8,1178.2 1345,1158 C3.2
GND: C1.1 C2.1 C3.1 C4.1 C5.1 C6.1 C7.1 C8.1 C9.1 C10.1 C11.2 C12.2 C13.1 C14.1 C15.1 C16.1 C17.1 C18.1 C19.1 C20.1 C21.1 J1.9 J1.10 J1.13 J1.16 J1.19 J1.22 J1.25 J1.28 J1.32 J1.33 J2.4 J2.7 J2.10 J2.13 J2.16 J2.19 J2.22 J2.23 J2.32 J2.33 JP1.1 JP1.4 JP1.7 JP1.10 JP1.13 JP1.16 JP1.19 JP2.1 JP2.11 JP2.14 JP2.17 JP2.20 JP2.23 JP3.0 JP3.7 M1.1 M2.1 M3.1 M4.1 R1.1 R3.1 R5.1 R6.1 U1.2 U2.2 U2.5 U3.2 U3.5 U4.11 U4.18 U4.20 U4.25 U5.2 U6.1 U7.2 | length 8082.4
  Top Layer w10: v1(1664.99,335.99) v1(1664.99,376.99)
  SIG w10: v1(858,1257) 858,1174 891.73,1140.27 v1(891.73,112.16)
  SIG w12: v1(911,1257) 911,1193 950.79,1153.21 v1(950.79,112.16) ; v1(970,1258) 970,1210 1009.84,1170.16 v1(1009.84,112.16) ; v1(1034,1258) 1034,1215 1068.9,1180.1 v1(1068.9,112.16)
  Bottom Layer w8: C14.1 v1(643,891.34) ; U4.11 688.51,734.82 U4.25 735.75,734.82 U4.20 v1(802.64,734.82) ; C13.1 v1(673,891.34) ; U4.18 v1(751.5,797.84)
  Bottom Layer w10: v1(727.27,150.73) 765.84,112.16 v1(891.73,112.16) JP1.1 ; v1(950.79,112.16) JP1.4 ; v1(1009.84,112.16) JP1.7 ; v1(1068.9,112.16) JP1.10 ; v1(1088.58,1277.58) JP2.14 ; v1(1147.64,1277.58) JP2.11 ; v1(1426.43,187.57) J2.33 ; v1(1510,611) 1571,611 1588.74,628.74 1660.63,628.74 1662.13,627.24 1681.59,627.24 1698.84,610 v1(1701,610) ; C3.1 v1(1556,1158) ; C4.1 v1(1556,1193) ; v1(1560,657) 1578.98,675.98 J1.13 1660.02,675.98 1674,662 v1(1696,662) ; v1(1582.32,144.43) J2.23 ; v1(1594.14,240.14) J2.22 v1(1594.14,353.86) ; v1(1596.85,746.85) J1.19 v1(1667.15,746.85) ; U1.2 v1(1617,1252) ; C1.1 v1(1656,1156) ; C2.1 v1(1656,1186) ; v1(1629.56,144.43) J2.19 ; J1.25 1665.06,817.71 1670.91,811.85 1670.91,798.09 v1(1671,798) 1692,798 1707.72,782.28 J1.22 ; v1(1649.49,418.51) J1.32 ; J1.33 1676.83,914.17 1682,909 v1(1682,887) ; J2.16 v1(1664.99,335.99) ; R3.1 v1(1711,1186) ; v1(1693,209) 1700.44,201.57 J2.13 v1(1700.44,144.43) ; v1(1735.86,253.14) J2.10 ; J1.10 v1(1782.45,640.55) ; J1.16 v1(1806.58,711.42) ; J1.28 1861.75,853.15 1874.9,840 v1(1877.06,840) ; J2.7 v1(1771.3,202.3) ; C6.1 v1(1826,1293) ; C7.1 v1(1826,1324) ; v1(1798,1158) C5.1 ; v1(1806.73,257.26) J2.4 ; J2.32 v1(1897.12,187.57) ; C9.1 v1(1925,1293) ; C10.1 v1(1925,1324) ; v1(1897,1158) C8.1
  Bottom Layer w12: C19.1 v1(176,204) ; v1(177,1431) R5.1 ; v1(230,1458) C16.1 ; v1(231,1339) U5.2 ; C15.1 245.5,1192.5 296.5,1192.5 v1(297,1193) ; C20.1 v1(338,583) ; C21.1 v1(370,583) ; v1(436,1431) R6.1 ; v1(471,1339) U7.2 ; v1(471,1457) C18.1 ; C17.1 v1(519,1189) ; v1(510.73,150.73) JP3.0@510.73,190.79 ; v1(521.6,732.4) C12.2 ; JP3.7 569.79,253.21 v1(586,237) ; C11.2 v1(637.06,605.4) ; v1(727.27,150.73) JP3.0@727.27,190.79 ; v1(1127.95,109.39) JP1.13 v1(1127.95,201.99) ; v1(1187.01,109.39) JP1.16 v1(1187.01,201.99) ; v1(1246.06,109.39) JP1.19 v1(1246.06,201.99) ; v1(1344.49,1286.14) JP2.1 ; v1(1351,946) R1.1
  other v1: 272.55,274 887,284 946,285 1005,286 1064,287 887,370 946,371 1005,372 1064,373 887,456 946,457 1005,458 1064,459 887,542 946,543 1005,544 1064,545 1504,550 1607,584 134,601 2062.06,601 887,628 946,629 1005,630 1064,631 134,660 2062.06,660 887,714 946,715 1005,716 1064,717 134,719 2062.06,719 134,778 2062.06,778 887,800 946,801 1005,802 1064,803 134,837 2062.06,837 887,886 946,887 1005,888 1064,889 134,896 2062.06,896 134,955 2062.06,955 887,972 946,973 1005,974 1064,975 134,1014 2062.06,1014 887,1058 946,1059 1005,1060 1064,1061 887,1144 946,1145 1005,1146 1064,1147 1770,1236 1869,1236
IMU_3V3: C11.1 C13.2 C14.2 L2.1 R4.1 U4.8 U4.13 | length 501
  Top Layer w12: v1(586.37,669.4) 586.37,783.71 595.13,792.46 v1(643,792.46)
  Bottom Layer w8: R4.1 564.06,788.4 570.06,794.4 608.06,794.4 613,799.34 L2.1 ; v1(586.37,669.4) C11.1 631.24,687.58 U4.8
  Bottom Layer w12: L2.1 C14.2 ; v1(643,792.46) C14.2 ; U4.13 672.76,822.76 C13.2 C14.2
IMU_CLK: JP3.2 U4.23 | length 557.2
  Bottom Layer w8: JP3.2 668.21,418.21 701.4,451.4 803.06,451.4 819.06,467.4 819.06,677.4 808.88,687.58 U4.23
IMU_CS: JP3.1 U4.22 | length 597
  Bottom Layer w8: JP3.1 687.9,407.9 712.4,432.4 825.06,432.4 840.06,447.4 840.06,686.4 823.13,703.33 U4.22
IMU_INT: R4.2 U4.12 | length 56.8
  Bottom Layer w8: R4.2 627.06,762.4 638.89,750.57 U4.12
IMU_MISO: JP3.4 U4.9 | length 508.6
  Bottom Layer w8: JP3.4 628.84,546.62 565.06,610.4 565.06,678 590.4,703.33 U4.9
IMU_MOSI: JP3.3 U4.24 | length 528.2
  Bottom Layer w8: JP3.3 648.53,437.53 678.4,467.4 787.06,467.4 799.06,479.4 799.06,666.4 793.63,671.83 U4.24
LED1_PWM: JP3.6 U5.4 | length 1216.4
  Top Layer w12: v1(268.4,1109.4) v1(268.4,1226)
  Bottom Layer w12: v1(268.4,1109.4) 268.4,961.6 290,940 383,940 408,915 408,500 445,463 551,463 589.47,424.53 JP3.6 ; v1(268.4,1226) U5.4
LED2_PWM: JP3.5 U7.4 | length 1199.3
  Bottom Layer w12: U7.4 v1(508.4,1226) 538,1226 553,1211 553,1165 498,1110 498,985 426,913 426,507.46 450.46,483 567,483 609.16,440.84 JP3.5
MIPI_TX0_N: J1.21 J2.11 | length 937.9
  SIG w4.79: v1(1666.97,770.47) 1682.29,785.79 1831.47,785.79 1862,755.26 1862,250.74 1829.22,217.97 1736.97,217.97 v1(1724.06,205.05)
  Bottom Layer w6: J1.21 v1(1666.97,770.47) ; J2.11 v1(1724.06,205.05)
MIPI_TX0_P: J1.20 J2.12 | length 942.6
  SIG w4.79: v1(1690.67,758.66) 1707.01,775 1827,775 1851.21,750.79 1851.21,255.21 1824.76,228.76 v1(1712.24,228.76)
  Bottom Layer w6: v1@1690.24,758.66 v1(1690.67,758.66) J1.20 ; v1@1712.24,228.33 v1(1712.24,228.76) J2.12
MIPI_TX1_N: J1.18 J2.14 | length 937.9
  SIG w4.79: v1(1688.62,256.95) 1673.79,271.79 1592.21,271.79 1576,288 1576,311.19 cw(c1582.24,311.19) 1582.24,317.42 1605.79,317.42 ccw(c1605.79,323.66) 1612.03,323.66 1612.03,331.98 ccw(c1605.79,331.98) 1605.79,338.21 1582.24,338.21 cw(c1582.24,344.45) 1576,344.45 1576,372 1576,390.61 1576,487.97 cw(c1582.24,487.97) 1582.24,494.21 1621.52,494.21 ccw(c1621.52,511.24) 1638.54,511.24 1638.54,519.55 ccw(c1621.52,519.55) 1621.52,536.58 1582.24,536.58 cw(c1582.24,542.82) 1576,542.82 1576,550.61 1576,616.74 1594.26,635 1709.26,635 1730.79,656.53 1730.79,723.12 v1(1718.87,735.04)
  Bottom Layer w6: v1(1688.62,256.95) J2.14 ; v1(1718.87,735.04) J1.18
MIPI_TX1_P: J1.17 J2.15 | length 938.8
  SIG w4.79: v1(1676.81,233.26) 1649.07,261 1587.74,261 1565.21,283.53 1565.21,390.61 1565.21,487.97 cw(c1582.24,487.97) 1582.24,505 1621.52,505 ccw(c1621.52,511.24) 1627.75,511.24 1627.75,519.55 ccw(c1621.52,519.55) 1621.52,525.79 1582.24,525.79 cw(c1582.24,542.82) 1565.21,542.82 1565.21,550.61 1565.21,621.21 1589.79,645.79 1704.79,645.79 1720,661 1720,698.4 v1(1695.17,723.23)
  Bottom Layer w6: J1.17 v1(1695.17,723.23) v1@1695.59,723.23 ; J2.15 v1(1676.81,233.26) v1@1676.81,233.68
MIPI_TX2_N: J1.15 J2.17 | length 940
  SIG w4.79: v1@1653.03,205.21 v1(1653.19,205.05) 1552.69,205.05 1530.37,227.37 1527.21,230.53 1527.21,247.16 1527.21,249.56 ccw(c1520.97,249.56) 1520.97,255.79 1509.84,255.79 cw(c1509.84,262.03) 1503.6,262.03 1503.6,270.35 cw(c1509.84,270.35) 1509.84,276.58 1520.97,276.58 ccw(c1520.97,282.82) 1527.21,282.82 1527.21,297.6 1527.21,334.23 1527.21,363.08 ccw(c1520.97,363.08) 1520.97,369.31 1517.7,369.31 cw(c1517.7,386.34) 1500.67,386.34 1500.67,394.66 cw(c1517.7,394.66) 1517.7,411.68 1521.01,411.68 ccw(c1521.01,417.92) 1527.24,417.92 1527.24,426.24 ccw(c1521.01,426.24) 1521.01,432.47 1492.82,432.47 cw(c1492.82,449.5) 1475.79,449.5 1475.79,457.82 cw(c1492.82,457.82) 1492.82,474.84 1520.97,474.84 ccw(c1520.97,481.08) 1527.21,481.08 1527.21,520.45 1527.21,664.47 1530.37,667.63 1550.74,688 1655.37,688 v1(1666.97,699.6)
  Bottom Layer w6: J1.15 v1(1666.97,699.6) ; J2.17 v1(1653.19,205.05)
MIPI_TX2_P: J1.14 J2.18 | length 940.7
  SIG w4.79: v1(1641.38,228.76) 1629.62,217 1556,217 1538,235 1538,334.23 1538,363.08 ccw(c1520.97,363.08) 1520.97,380.1 1517.7,380.1 cw(c1517.7,386.34) 1511.46,386.34 1511.46,394.66 cw(c1517.7,394.66) 1517.7,400.89 1521.01,400.89 ccw(c1521.01,417.92) 1538.03,417.92 1538.03,426.24 ccw(c1521.01,426.24) 1521.01,443.26 1492.82,443.26 cw(c1492.82,449.5) 1486.58,449.5 1486.58,457.82 cw(c1492.82,457.82) 1492.82,464.05 1520.97,464.05 ccw(c1520.97,481.08) 1538,481.08 1538,520.45 1538,660 1555.21,677.21 1680.09,677.21 v1(1690.67,687.79)
  Bottom Layer w6: v1@1641.38,228.33 v1(1641.38,228.76) J2.18 ; v1@1690.24,687.79 v1(1690.67,687.79) J1.14
NetC12_1: C12.1 U4.10 | length 57.4
  Bottom Layer w8: C12.1 628.06,732.4 641.39,719.07 U4.10
NetC16_2: C16.2 D1.1 LED1.2 U5.5 | length 324.5
  Top Layer w12: v1(121,1489) 121,1320 139,1302 v1(231,1302)
  Bottom Layer w12: U5.5 v1(231,1302)
  other v1: 103,1516 138,1516
NetC18_2: C18.2 D2.1 LED3.2 U7.5 | length 495.1
  Top Layer w12: v1(361,1489) 328.37,1489 318.82,1479.45 318.82,1466.03 311.79,1459 279,1459 268,1448 268,1318.64 284.64,1302 v1(471,1302)
  Bottom Layer w12: U7.5 v1(471,1302)
  other v1: 343,1516 378,1516
NetD1_2: D1.2 L3.2 U5.1
NetD2_2: D2.2 L4.2 U7.1
NetL1_1: L1.1 U1.4
NetLED1_1: LED1.1 LED2.2 | length 2007.9
  Top Layer w28: LED1.1 219,1581 238,1562 445,1562 525,1482 861,1482 950,1393 1246,1393 1335,1482 1667,1482 1746,1561 1966,1561 1979,1574 LED2.2
NetLED2_1: LED2.1 R5.2 U5.3 | length 1915.7
  Top Layer w28: v1(302,1431) 356,1431 400,1387 859.83,1387 921.83,1325 1274.17,1325 1363.17,1414 1941,1414 1979,1452 LED2.1
  Bottom Layer w12: R5.2 268.4,1430.6 U5.3
  Bottom Layer w28: R5.2 v1(302,1431)
NetLED3_1: LED3.1 LED4.2 | length 1632
  Top Layer w28: LED3.1 438.98,1625.02 547.65,1516.35 875.65,1516.35 965,1427 1231,1427 1320.35,1516.35 1648.35,1516.35 1757.02,1625.02 LED4.2
NetLED4_1: LED4.1 R6.2 U7.3 | length 1459.2
  Top Layer w28: v1(561,1431) 863.92,1431 935.92,1359 1260.08,1359 1349.08,1448 1681.08,1448 1736.06,1502.98 LED4.1
  Bottom Layer w12: U7.3 508.4,1412.4 R6.2
  Bottom Layer w28: R6.2 v1(561,1431)
NetR2_1: R2.1 R3.2 U1.1 | length 77.5
  Bottom Layer w10: U1.1 1681.43,1225.43 R3.2 R2.1
PVCC: C15.2 C17.2 C19.2 JP3.8 L3.1 L4.1 U5.6 U6.3 U7.6
pads on no net: JP1.0 JP1.11 JP1.12 JP1.14 JP1.15 JP2.0 JP2.3 JP2.12 JP2.13 JP2.15 JP2.16 JP2.26 U1.6 U4.1 U4.2 U4.3 U4.4 U4.5 U4.6 U4.7 U4.14 U4.15 U4.16 U4.17 U4.19 U4.21

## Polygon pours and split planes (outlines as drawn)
GND on Bottom Layer "GND_L04_P020" (solid, remove dead copper, pour order 20): -3.02,0 -3.02,80 -2.13,82.13 34.98,119.25 34.98,1372.75 -2.13,1409.87 -3.02,1412 -3.02,1492 cw(c120.71,1492) 33.22,1579.49 130.51,1676.78 cw(c218,1589.29) 218,1713.02 365,1713.02 cw(c365,1589.29) 452.49,1676.78 536.78,1592.49 ccw(c620,1675.71) 620,1558.02 689.15,1558.02 ccw(c689.15,1639.14) 746.51,1581.78 ccw(c663.29,1665) 780.98,1665 780.98,1703 cw(c904.71,1703) 817.22,1790.49 885.94,1859.2 cw(c973.42,1771.71) 973.42,1895.44 1223.42,1895.44 cw(c1223.42,1771.71) 1310.91,1859.2 1379.63,1790.49 cw(c1292.14,1703) 1415.86,1703 1415.86,1665 ccw(c1533.56,1665) 1450.34,1581.78 ccw(c1507.7,1639.14) 1507.7,1558.02 1576.85,1558.02 ccw(c1576.85,1675.71) 1660.07,1592.49 1744.36,1676.78 cw(c1831.85,1589.29) 1831.85,1713.02 1978.85,1713.02 cw(c1978.85,1589.29) 2066.34,1676.78 2163.63,1579.49 cw(c2076.14,1492) 2199.86,1492 2199.86,1422.83 2199.87,0 2196.85,-3.01
PVCC on Bottom Layer "PVCC_L04_P016" (solid, remove dead copper, pour order 16): 113,188 113,1059 190,1136 66,1136 66,188
PVCC on Bottom Layer "PVCC_L04_P017" (solid, remove dead copper, pour order 17): 558,313 558,250 522,214 439,214 339,114 82,114 66,130 66,188 113,188 113,161 121,153 305,153 405,253 508,253 531,276 531,313
PVCC on Bottom Layer "PVCC_L04_P015" (solid, remove dead copper, pour order 15): 443,1285 443,1142 424.95,1123.95 66,1123.95 66,1285 176,1285 203,1285 203,1210 203,1170 213,1160 304,1160 314,1170 314,1276 323,1285
NetD2_2 on Bottom Layer "NETD2_2_L04_P014" (solid, remove dead copper, pour order 14): 443,1394 323,1394 314,1385 314,1306 414,1306 443,1335
NetD1_2 on Bottom Layer "NETD1_2_L04_P013" (solid, remove dead copper, pour order 13): 203,1394 83,1394 74,1385 74,1306 174,1306 203,1335
NetC18_2 on Bottom Layer "NETC18_2_L04_P011" (solid, remove dead copper, pour order 11): 326,1475 326,1534 441,1534 441,1475 415,1475
NetC16_2 on Bottom Layer "NETC16_2_L04_P009" (solid, remove dead copper, pour order 9): 86,1475 86,1534 201,1534 201,1475 175,1475
CAM_3V3 on Bottom Layer "CAM_3V3_L04_P008" (solid, remove dead copper, pour order 8): 1570,1139 1866.06,1139 1866.06,1110.4 1581.06,1110.4 1570,1121.46
DOVDD_1V8 on Bottom Layer "DOVDD_1V8_L04_P007" (solid, remove dead copper, pour order 7): 1862.11,1252.73 1862.11,1277.11 1866,1281 1866,1303 1846,1303 1846,1236
CAM_3V3 on Bottom Layer "CAM_3V3_L04_P006" (solid, remove dead copper, pour order 6): 1850,1229 1850,1196 1847,1193 1847,1178 1850,1175 1864,1175 1867,1178 1867,1192 1862,1197 1862,1217
CAM_3V3 on Bottom Layer "CAM_3V3_L04_P004" (solid, remove dead copper, pour order 4): 1751,1229 1751,1196 1748,1193 1748,1178 1751,1175 1765,1175 1768,1178 1768,1192 1763,1197 1763,1217
AVDD_2V8 on Bottom Layer "AVDD_2V8_L04_P003" (solid, remove dead copper, pour order 3): 1763.11,1252.73 1763.11,1277.11 1767,1281 1767,1303 1747,1303 1747,1236
DVDD_1V2 on Bottom Layer "DVDD_1V2_L04_P002" (solid, remove dead copper, pour order 2): 1555,1214 1506,1214 1500,1208 1500,1142 1471,1142 1471,1237 1481,1247 1555,1247
NetL1_1 on Bottom Layer "NETL1_1_L04_P001" (solid, remove dead copper, pour order 1): 1604,1269 1497,1269 1497,1291.08 1604,1291.08
CAM_3V3 on Bottom Layer "CAM_3V3_L04_P000" (solid, remove dead copper, pour order 0): 1607,1238 1607,1133 1324,850 1324,126 1295,126 1295,864 1570,1139 1570,1201 1587,1218 1587,1238
GND on Top Layer "GND_L01_P018" (solid, remove dead copper, pour order 18): -3.02,0 -3.02,80 -2.13,82.13 34.98,119.25 34.98,1372.75 -2.13,1409.87 -3.02,1412 -3.02,1492 cw(c120.71,1492) 33.22,1579.49 130.51,1676.78 cw(c218,1589.29) 218,1713.02 365,1713.02 cw(c365,1589.29) 452.49,1676.78 536.78,1592.49 ccw(c620,1675.71) 620,1558.02 689.15,1558.02 ccw(c689.15,1639.14) 746.51,1581.78 ccw(c663.29,1665) 780.98,1665 780.98,1703 cw(c904.71,1703) 817.22,1790.49 885.94,1859.2 cw(c973.42,1771.71) 973.42,1895.44 1223.42,1895.44 cw(c1223.42,1771.71) 1310.91,1859.2 1379.63,1790.49 cw(c1292.14,1703) 1415.86,1703 1415.86,1665 ccw(c1533.56,1665) 1450.34,1581.78 ccw(c1507.7,1639.14) 1507.7,1558.02 1576.85,1558.02 ccw(c1576.85,1675.71) 1660.07,1592.49 1744.36,1676.78 cw(c1831.85,1589.29) 1831.85,1713.02 1978.85,1713.02 cw(c1978.85,1589.29) 2066.34,1676.78 2163.63,1579.49 cw(c2076.14,1492) 2199.86,1492 2199.86,1422.83 2199.87,0 2196.85,-3.01
NetC18_2 on Top Layer "NETC18_2_L01_P012" (solid, remove dead copper, pour order 12): 326,1534 441,1534 441,1475 326,1475
NetC16_2 on Top Layer "NETC16_2_L01_P010" (solid, remove dead copper, pour order 10): 86,1534 201,1534 201,1475 86,1475
GND on SIG "GND_L03_P019" (solid, remove dead copper, pour order 19): -3.02,0 -3.02,80 -2.13,82.13 34.98,119.25 34.98,1372.75 -2.13,1409.87 -3.02,1412 -3.02,1492 cw(c120.71,1492) 33.22,1579.49 130.51,1676.78 cw(c218,1589.29) 218,1713.02 365,1713.02 cw(c365,1589.29) 452.49,1676.78 536.78,1592.49 ccw(c620,1675.71) 620,1558.02 689.15,1558.02 ccw(c689.15,1639.14) 746.51,1581.78 ccw(c663.29,1665) 780.98,1665 780.98,1703 cw(c904.71,1703) 817.22,1790.49 885.94,1859.2 cw(c973.42,1771.71) 973.42,1895.44 1223.42,1895.44 cw(c1223.42,1771.71) 1310.91,1859.2 1379.63,1790.49 cw(c1292.14,1703) 1415.86,1703 1415.86,1665 ccw(c1533.56,1665) 1450.34,1581.78 ccw(c1507.7,1639.14) 1507.7,1558.02 1576.85,1558.02 ccw(c1576.85,1675.71) 1660.07,1592.49 1744.36,1676.78 cw(c1831.85,1589.29) 1831.85,1713.02 1978.85,1713.02 cw(c1978.85,1589.29) 2066.34,1676.78 2163.63,1579.49 cw(c2076.14,1492) 2199.86,1492 2199.86,1422.83 2199.87,0 2196.85,-3.01
GND on GND (split plane): 408 vertices, not listed, extent 17.08,17.11 2179.77,1875.34

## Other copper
Top Layer:
  text "1-TOP 2-GND 3-SIG 4-BOT" at 413,-157 h60

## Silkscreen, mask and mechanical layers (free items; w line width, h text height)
Top Overlay:
  lines w6: 460.24,427.24 460.24,994.17 1405.12,994.17 1405.12,427.24 460.24,427.24 ; 1594.09,427.24 1594.09,994.17 1735.83,994.17 1735.83,427.24 1594.09,427.24
  lines w12: 350,317 350,1104.4 1846.06,1104.4 1846.06,317 350,317
  text "1 - 31" at 1850,556 h60 r90
  text "1 - 31" at 1522,68 h60
Mechanical 1:
  circle w10: c1098.43,1661.4 r196.85
  lines w6: 0,1422.83 0,1492 ; 0,1492 cw(c120.71,1492) 35.36,1577.36 132.64,1674.64 cw(c218,1589.29) 218,1710 365,1710 cw(c365,1589.29) 450.36,1674.64 534.64,1590.36 ccw(c620,1675.71) 620,1555 689.15,1555 ccw(c689.15,1639.14) 748.64,1579.64 ccw(c663.29,1665) 784,1665 784,1703 cw(c904.71,1703) 819.36,1788.36 888.07,1857.07 cw(c973.42,1771.71) 973.42,1892.42 1098.42,1892.42 1223.42,1892.42 cw(c1223.42,1771.71) 1308.78,1857.07 1377.49,1788.36 cw(c1292.14,1703) 1412.85,1703 1412.85,1665 ccw(c1533.56,1665) 1448.21,1579.64 ccw(c1507.7,1639.14) 1507.7,1555 1576.85,1555 ccw(c1576.85,1675.71) 1662.21,1590.36 1746.49,1674.64 cw(c1831.85,1589.29) 1831.85,1710 1978.85,1710 cw(c1978.85,1589.29) 2064.21,1674.64 2161.49,1577.36 cw(c2076.14,1492) 2196.85,1492 2196.85,1422.83 2196.85,0 0,0 0,80 38,118 38,1374 0,1412 0,1492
